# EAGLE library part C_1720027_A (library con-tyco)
Serial ATA & Serial Attached SCSI Source: http://catalog.tycoelectronics.com .. C_1720027_A.pdf
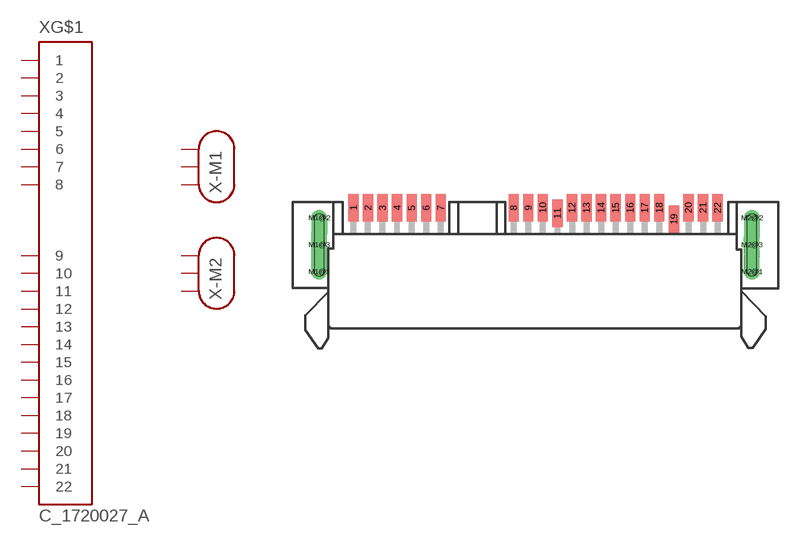
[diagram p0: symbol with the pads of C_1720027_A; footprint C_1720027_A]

Designator prefix X; gates G$1=SERIAL_ATA-SERIAL_ATTACHED_SCSI -M1=MECH-PAD3 -M2=MECH-PAD3

## C_1720027_A (OC_FARNELL: unknown; OC_NEWARK: unknown)  [C_1720027_A]
1  G$1:1  pas
2  G$1:2  pas
3  G$1:3  pas
4  G$1:4  pas
5  G$1:5  pas
6  G$1:6  pas
7  G$1:7  pas
8  G$1:8  pas
9  G$1:9  pas
10  G$1:10  pas
11  G$1:11  pas
12  G$1:12  pas
13  G$1:13  pas
14  G$1:14  pas
15  G$1:15  pas
16  G$1:16  pas
17  G$1:17  pas
18  G$1:18  pas
19  G$1:19  pas
20  G$1:20  pas
21  G$1:21  pas
22  G$1:22  pas
M1@1  -M1:M  pas
M1@2  -M1:M  pas
M1@3  -M1:M  pas
M2@1  -M2:M  pas
M2@2  -M2:M  pas
M2@3  -M2:M  pas

## Footprint C_1720027_A (pad centres in mm)
Serial ATA & Serial Attached SCSI Source: http://catalog.tycoelectronics.com .. C_1720027_A.pdf
smd 0.9 x 2.4: 1 -15.88,3.24; 2 -14.61,3.24; 3 -13.34,3.24; 4 -12.07,3.24; 5 -10.8,3.24; 6 -9.53,3.24; 7 -8.26,3.24; 8 -1.9,3.24; 9 -0.63,3.24; 10 0.64,3.24; 11 1.91,2.74; 12 3.18,3.24; 13 4.45,3.24; 14 5.72,3.24; 15 6.99,3.24; 16 8.26,3.24; 17 9.53,3.24; 18 10.8,3.24; 19 12.07,2.24; 20 13.34,3.24; 21 14.61,3.24; 22 15.88,3.24
drill 0.8 pad 1.4 offset: M1@1 -18.87,-2.35; M1@2 -18.87,2.35; M2@1 18.87,-2.35; M2@2 18.87,2.35
drill 0.8 pad 1.4 long: M1@3 -18.87,0; M2@3 18.87,0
